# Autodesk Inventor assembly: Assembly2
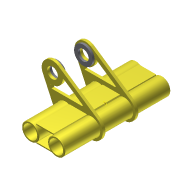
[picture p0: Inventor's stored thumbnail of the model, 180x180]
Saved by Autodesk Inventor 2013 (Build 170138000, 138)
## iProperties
Created: 2012-04
Part Number: Assembly2
Document SubType Name: Assembly
Designer: Dale
Author: Dale
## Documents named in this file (7)
- C:\Product Design Suite 2013 Test Drive\Inventor Optimization\Workspace\Assembly2.iam
- C:\Product Design Suite 2013 Test Drive\Inventor Optimization\Workspace\Assy, Chassis, Front\PK46.25.01.005.ipt
- C:\Product Design Suite 2013 Test Drive\Inventor Optimization\Workspace\Assy, Chassis, Front\PK46.25.01.006.ipt
- C:\Product Design Suite 2013 Test Drive\Inventor Optimization\Workspace\Assy, Chassis, Front\PK46.25.01.007.ipt
- C:\Product Design Suite 2013 Test Drive\Inventor Optimization\Workspace\Assy, Chassis, Front\PK46.25.01.009.ipt
- C:\Product Design Suite 2013 Test Drive\Inventor Optimization\Workspace\Assy, Chassis, Front\PK46.25.01.009-01.ipt
- C:\Product Design Suite 2013 Test Drive\Inventor Optimization\Workspace\Assy, Chassis, Front\PK46.25.01.016.ipt
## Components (12 placed, 6 different names)
1. PK46.25.01.005:1
2. PK46.25.01.005:2
3. PK46.25.01.006:1
4. PK46.25.01.006:2
5. PK46.25.01.007:1
6. PK46.25.01.007:2
7. PK46.25.01.009:1
8. PK46.25.01.009-01:1
9. PK46.25.01.009-01:2
10. PK46.25.01.009-01:3
11. PK46.25.01.009-01:4
12. PK46.25.01.016:1
## Named parameters: d5_d12 = 0, d6_d15 = 0, d7_d18 = 0
